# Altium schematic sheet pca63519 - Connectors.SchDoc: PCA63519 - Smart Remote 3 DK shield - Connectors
size A4; DocumentNumber: 1; Revision: 1.2.1; SheetNumber: 1; SheetTotal: 6; DrawnBy: GETR; ProjectNumber: 4414; DocumentSize: A4; PCBRevision: 0049GETR; PCAName: PCA63519; PCBNumber: 400129
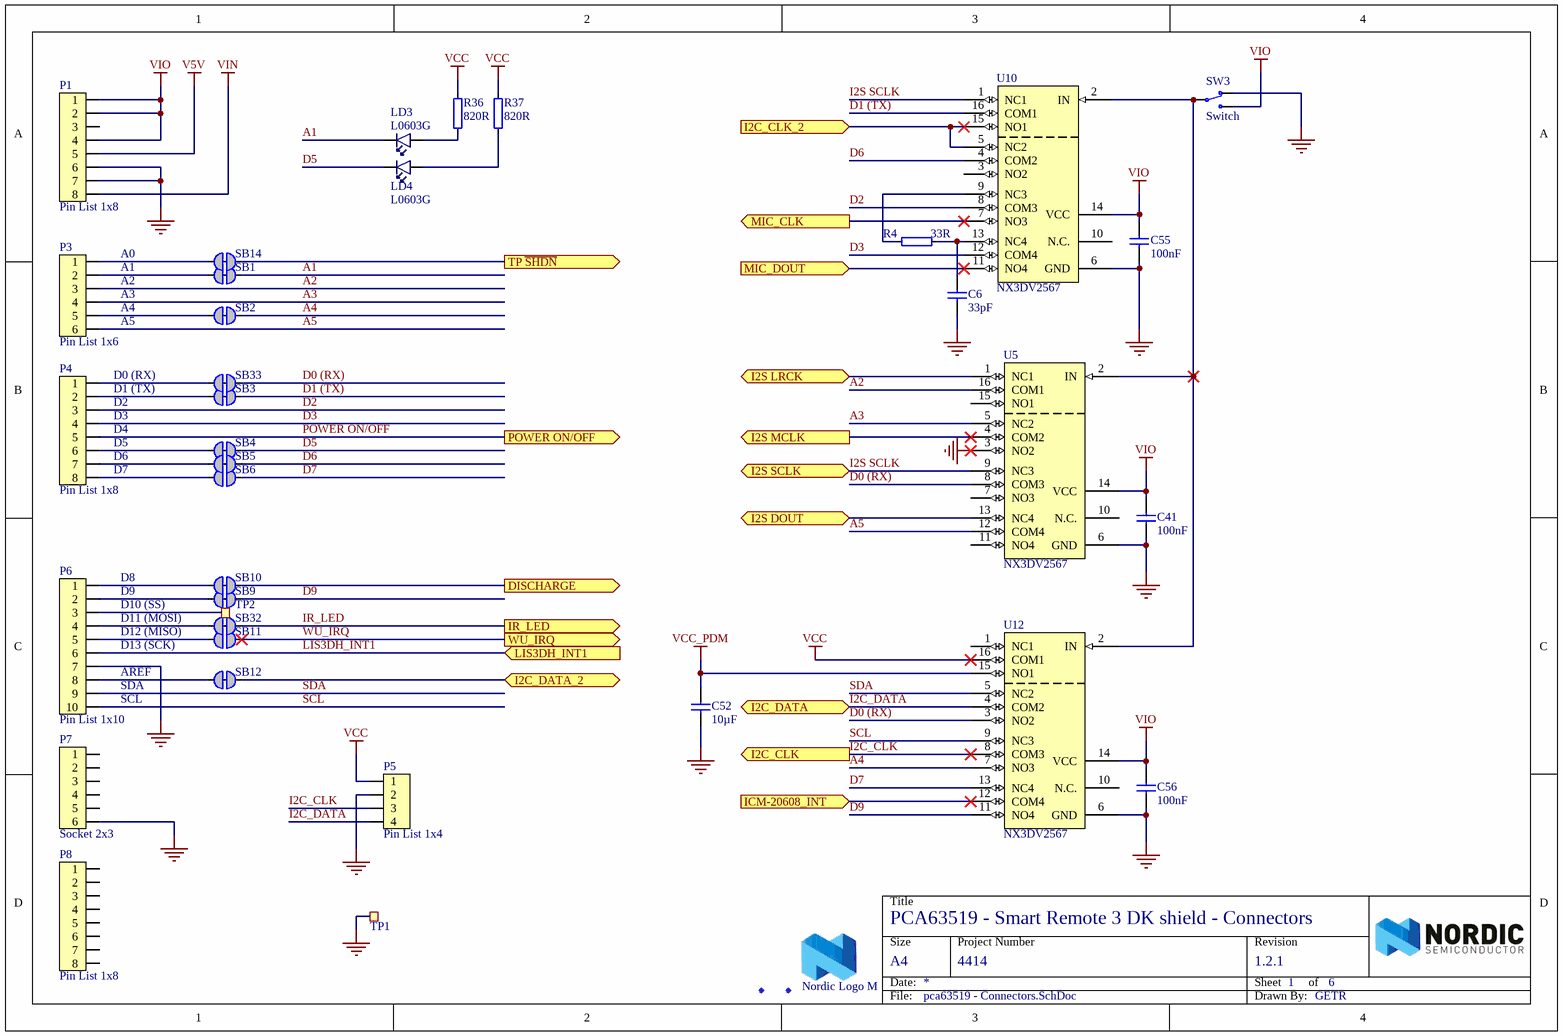
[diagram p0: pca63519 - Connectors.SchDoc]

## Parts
C6  33pF  [CAPC1005X04L]
C41  100nF  [CAPC1005X04L]
C52  10µF  [CAPC1005X04L]
C55  100nF  [CAPC1005X04L]
C56  100nF  [CAPC1005X04L]
Fid1  Fiducial mark  [Fiducial]  (value not drawn)
Fid2  Fiducial mark  [Fiducial]  (value not drawn)
LD3  L0603G  [LED_0603_G]
LD4  L0603G  [LED_0603_G]
LOGO1  Nordic Logo M  [NORDIC_LOGO_M]  (no BOM)
P1  Pin List 1x8  [LIST_1x8_SMD]
P3  Pin List 1x6  [LIST_1x6_SMD]
P4  Pin List 1x8  [LIST_1x8_SMD]
P5  Pin List 1x4  [LIST_1x4]
P6  Pin List 1x10  [LIST_1x10_SMD]
P7  Socket 2x3  [SOCKET_2x3_SMD-2.54mm-bottom]
P8  Pin List 1x8  [LIST_1x8_SMD]
R4  33R  [RESC1005X04L]
R36  820R  [RESC1005X04L]
R37  820R  [RESC1005X04L]
SB1  Solderbridge  [Solderbridge_SHORTED_0.4]  (value not drawn)  (net tie, no BOM)
SB2  Solderbridge  [Solderbridge_SHORTED_0.4]  (value not drawn)  (net tie, no BOM)
SB3  Solderbridge  [Solderbridge_SHORTED_0.4]  (value not drawn)  (net tie, no BOM)
SB4  Solderbridge  [Solderbridge_SHORTED_0.4]  (value not drawn)  (net tie, no BOM)
SB5  Solderbridge  [Solderbridge_SHORTED_0.4]  (value not drawn)  (net tie, no BOM)
SB6  Solderbridge  [Solderbridge_0.4]  (value not drawn)  (no BOM)
SB9  Solderbridge  [Solderbridge_SHORTED_0.4]  (value not drawn)  (net tie, no BOM)
SB10  Solderbridge  [Solderbridge_SHORTED_0.4]  (value not drawn)  (net tie, no BOM)
SB11  Solderbridge  [Solderbridge_0.4]  (value not drawn)  (no BOM)
SB12  Solderbridge  [Solderbridge_SHORTED_0.4]  (value not drawn)  (net tie, no BOM)
SB14  Solderbridge  [Solderbridge_SHORTED_0.4]  (value not drawn)  (net tie, no BOM)
SB32  Solderbridge  [Solderbridge_SHORTED_0.4]  (value not drawn)  (net tie, no BOM)
SB33  Solderbridge  [Solderbridge_SHORTED_0.4]  (value not drawn)  (net tie, no BOM)
SW3  Switch  [CJS-120xA]
TP1  Ø1.0mm,SMD  [TP_SMD_Ø1.0mm]  (value not drawn)  (no BOM)
TP2  Ø1.0mm,SMD  [TP_SMD_Ø1.0mm]  (value not drawn)  (no BOM)
U5  NX3DV2567  [XQFN40P180X260X50-16N]
U10  NX3DV2567  [XQFN40P180X260X50-16N]
U12  NX3DV2567  [XQFN40P180X260X50-16N]

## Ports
DISCHARGE (out), I2C_CLK (out), I2C_CLK_2 (in), I2C_DATA (bidir), I2C_DATA_2 (bidir), I2S DOUT (bidir), I2S LRCK (bidir), I2S MCLK (out), I2S SCLK (bidir), ICM-20608_INT (in), IR_LED (out), LIS3DH_INT1 (in), MIC_CLK (out), MIC_DOUT (in), POWER ON/OFF (out), TP ~{SHDN} (out), WU_IRQ (out)

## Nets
GND: C6.1 C41.1 C52.1 C55.1 C56.1 P1.6 P1.7 P5.2 P6.7 P7.6 SW3.1(N.C) TP1.1 U5.3(NO2) U5.6(GND) U10.6(GND) U12.6(GND)
V5V: P1.5
VCC: P5.1 R36.2 R37.2 U12.16(COM1)
VCC_PDM: C52.2 U12.15(NO1)
VIN: P1.8
VIO: C41.2 C55.2 C56.2 P1.1 P1.2 P1.4 SW3.3(N.O) U5.14(VCC) U10.14(VCC) U12.14(VCC)
A1: LD3.1(C) SB1.1
A2: P3.3 U5.16(COM1)
A3: P3.4 U5.5(NC2)
A4: SB2.1 U12.7(NO3)
A5: P3.6 U5.12(COM4)
D0 (RX): SB33.1 U5.8(COM3) U12.3(NO2)
D1 (TX): SB3.1 U10.16(COM1)
D2: P4.3 U10.8(COM3)
D3: P4.4 U10.12(COM4)
D5: LD4.1(C) SB4.1
D6: SB5.1 U10.4(COM2)
D7: SB6.1 U12.13(NC4)
D9: SB9.1 U12.11(NO4)
DISCHARGE: SB10.1 ; port DISCHARGE
I2C_CLK: P5.3 U12.8(COM3) ; port I2C_CLK
I2C_CLK_2: U10.5(NC2) U10.15(NO1) ; port I2C_CLK_2
I2C_DATA: P5.4 U12.4(COM2) ; port I2C_DATA
I2C_DATA_2: SB12.1 ; port I2C_DATA_2
I2S DOUT: U5.13(NC4) ; port I2S DOUT
I2S LRCK: U5.1(NC1) ; port I2S LRCK
I2S MCLK: U5.4(COM2) ; port I2S MCLK
I2S SCLK: U5.9(NC3) U10.1(NC1) ; port I2S SCLK
ICM-20608_INT: U12.12(COM4) ; port ICM-20608_INT
IR_LED: SB32.1 ; port IR_LED
LIS3DH_INT1: P6.6 ; port LIS3DH_INT1
MIC_CLK: U10.7(NO3) ; port MIC_CLK
MIC_DOUT: U10.11(NO4) ; port MIC_DOUT
POWER ON/OFF: P4.5 ; port POWER ON/OFF
SCL: P6.10 U12.9(NC3)
SDA: P6.9 U12.5(NC2)
TP ~{SHDN}: SB14.1 ; port TP ~{SHDN}
WU_IRQ: SB11.1 ; port WU_IRQ
NetC6_2: C6.2 R4.2 U10.13(NC4)
NetLD3_2: LD3.2(A) R36.1
NetLD4_2: LD4.2(A) R37.1
NetP3_1: P3.1 SB14.2
NetP3_2: P3.2 SB1.2
NetP3_5: P3.5 SB2.2
NetP4_1: P4.1 SB33.2
NetP4_2: P4.2 SB3.2
NetP4_6: P4.6 SB4.2
NetP4_7: P4.7 SB5.2
NetP4_8: P4.8 SB6.2
NetP6_1: P6.1 SB10.2
NetP6_2: P6.2 SB9.2
NetP6_3: P6.3 TP2.1
NetP6_4: P6.4 SB32.2
NetP6_5: P6.5 SB11.2
NetP6_8: P6.8 SB12.2
NetR4_1: R4.1 U10.9(NC3)
NetSW3_2: SW3.2(COM) U5.2(IN) U10.2(IN) U12.2(IN)

Not connected (* = marked no-connect by the designer): P1 3; P7 1 2 3 4 5; P8 1 2 3 4 5 6 7 8; U5 7(NO3) 10(N.C.) 11(NO4) 15(NO1); U10 3(NO2) 10(N.C.); U12 1(NC1) 10(N.C.)

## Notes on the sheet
- (near P3) A0
- (near P3) A1
- (near P3) A2
- (near P3) A3
- (near P3) A4
- (near P4) D0 (RX)
- (near P3) A5
- (near P4) D1 (TX)
- (near P4) D2
- (near P4) D3
- (near P4) D4
- (near P4) D5
- (near P4) D6
- (near P4) D7
- (near P6) D8
- (near P6) D9
- D10 (SS)
- D11 (MOSI)
- D12 (MISO)
- D13 (SCK)
- (near P6) AREF
- (near P6) SDA
- (near P6) SCL

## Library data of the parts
C6 = C0402-33p: Capacitor, NP0, ±5%; Note: 50V; Artikkelnr Noca: 20029146; Artikkelnr Simpro: N.A.
C41 C55 C56 = C0402-100n: Capacitor, X7R, ±10%; Note: 16V; Artikkelnr Noca: 20039200; Artikkelnr Simpro: N.A.
C52 = C0402-10µF: 10µF ±20% 10V X5R Ceramic Capacitor -55°C ~ 85°C Surface Mount, MLCC 0402; Manufacturer: Samsung; Manufacturer Part Number: CL05A106MP5NUNC; Artikkelnr Noca: N.A.
Fid1 Fid2 = Fid-Mark: Artikkelnr Noca: N.A.
LD3 LD4 = LG L29K Smartled Green: LED SMARTLED GREEN 570NM 0603; Manufacturer: Osram; Manufacturer Part Number: LG L29K-G2J1-24-Z; 2nd source part number: 720-LGL29KG2J124Z; Note: 2,24..5.6 mcd, Vfmin=1.7V; Artikkelnr Noca: 13019147; Artikkelnr Simpro: N.A.
LOGO1 = Nordic Logo M: Nordic Logo, medium size; Artikkelnr Noca: N.A.
P1 P4 P8 = Pin List 1x8 SMD: Pin List 1x8, 2.54mm (100mil), SMD; Manufacturer: W-CON; Manufacturer Part Number: 1125-1108S0M116R2; 2nd source part number: TSM-108-01-L-SV-P-TR; Artikkelnr Noca: 55010006; Artikkelnr Simpro: N.A.
P3 = Pin List 1x6 SMD: Pin List 1x6, 2.54mm (100mil), SMD; Manufacturer: W-CON; Manufacturer Part Number: 1125-1106S0M116R2; 2nd source part number: TSM-106-01-L-SV-P-TR; Artikkelnr Noca: 55010026; Artikkelnr Simpro: N.A.
P5 = Pin List 1x4: Pin List 1x4, 2.54mm (100mil); Artikkelnr Noca: 56019092; Artikkelnr Simpro: N.A.
P6 = Pin List 1x10 SMD: Pin List 1x10, 2.54mm (100mil), SMD; Manufacturer: W-CON; Manufacturer Part Number: 1125-1110S0M116R2; 2nd source part number: TSM-110-01-L-SV-P-TR; Artikkelnr Noca: 55010028; Artikkelnr Simpro: N.A.
P7 = Socket 2x3 SMD Bottom: Socket 2x3, 2.54mm (100mil), SMD; Manufacturer: W-CON; Manufacturer Part Number: 2171-203MS0CUNR1; 2nd source part number: SSM-103-F-DV-P-TR; Artikkelnr Noca: 55030010; Artikkelnr Simpro: N.A.
R4 = R0402-33R: Resistor, ±1%, 0.063W; Note: Chip Res 1%; Artikkelnr Noca: 27049037; Artikkelnr Simpro: N.A.; Value Ohm: 33
R36 R37 = R0402-820: Resistor, ±1%, 0.063W; Note: Chip Res 1%; Artikkelnr Noca: 27049071; Artikkelnr Simpro: N.A.; Value Ohm: 820
SB1-SB5 SB9 SB10 SB12 SB14 SB32 SB33 = Solderbridge Shorted 0.4mm: Shorted Solderbridge; Artikkelnr Noca: N.A.
SB6 SB11 = Solderbridge 0.4mm: Artikkelnr Noca: N.A.
SW3 = CJS-1200TA: SMD slide Switch (ON-ON); Manufacturer: Copal Electronics Inc; Artikkelnr Noca: 50019068; Artikkelnr Simpro: N.A.
TP1 TP2 = TP_SMD_Ø1.0MM: 1.0mm circular SMD testpad; Manufacturer: Nordic Semiconductor; Artikkelnr Noca: N.A.
U5 U10 U12 = NX3DV2567GU: Low-ohmic four-pole double-throw analog switch; Manufacturer: NXP Semiconductors; 2nd source part number: 771-NX3DV2567GU115; Artikkelnr Noca: 15079317; Artikkelnr Simpro: N.A.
